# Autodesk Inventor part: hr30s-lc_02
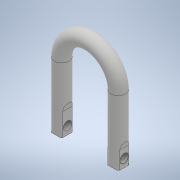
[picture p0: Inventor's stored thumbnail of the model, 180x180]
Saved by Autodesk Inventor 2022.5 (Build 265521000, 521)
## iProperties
Part Number: hr30s-lc_02
Material: 一般
Document SubType Name: Modeling
Designer: ImaoCorp
Density: 1 g/cm^3
Appearance: 既定
Author: ImaoCorp
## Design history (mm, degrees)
feature "hr30s-lc_02"
node "ソリッド1"
